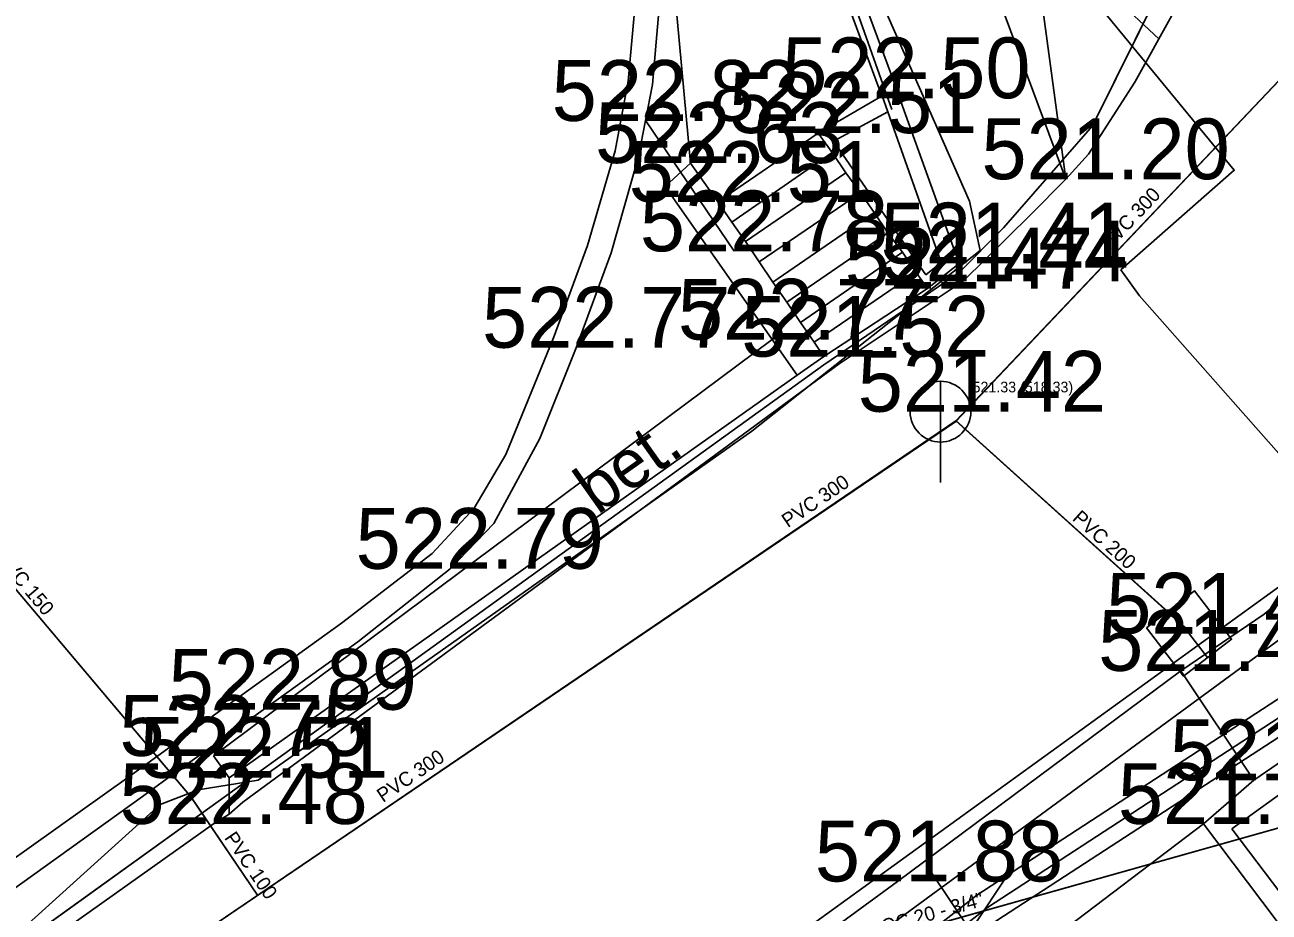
# Model space of a CAD drawing. Extents: x -668867 to -667827, y -1131943 to -1131019.
# Drawn here: x -668551.42 to -668536.05, y -1131435.74 to -1131424.78 of the extents above; entities that cross this region are included whole.
import ezdxf

# ---------------------------------------------------------------- set-up
doc = ezdxf.new("R2010")
doc.units = 0
for name, color, linetype in [('G_Bod_tecka', 7, 'Continuous'), ('G_Bod_vyska', 7, 'Continuous'), ('G_Breh_Teren', 7, 'Continuous'), ('G_Cesty_Schody', 7, 'Continuous'), ('G_Plochy_zpevnene', 7, 'Continuous'), ('G_Ploty', 7, 'Continuous'), ('G_Ploty_vstupy', 7, 'Continuous'), ('G_Popisy_povrchu', 7, 'Continuous'), ('G_Site-kanalizace', 7, 'Continuous'), ('G_Vyskove_srafy', 7, 'Continuous'), ('G_Z_CHRANICKA-TEPLOVOD_kotovane', 7, 'Continuous'), ('G_Z_ELsilove_podz_kotovane', 7, 'Continuous'), ('G_Z_KANAL_podz_kotovane', 7, 'Continuous'), ('G_Z_PLYNY_podz_geodeticky', 7, 'Continuous'), ('G_Z_SPOJE_podz_geodeticky', 7, 'Continuous'), ('G_Z_SPOJE_podz_kotovane', 7, 'Continuous'), ('G_Z_SPOJE_podz_priblizne', 7, 'Continuous'), ('G_Z_VODA_podz_kotovane', 7, 'Continuous'), ('G_Zabradli_Svodidla', 7, 'Continuous'), ('G_Zelen-Znacky', 7, 'Continuous'), ('Vrstva 12', 7, 'Continuous'), ('Vrstva 17', 7, 'Continuous'), ('Vrstva 2', 7, 'Continuous'), ('Vrstva 25', 7, 'Continuous'), ('Vrstva 3', 7, 'Continuous'), ('Vrstva 4', 7, 'Continuous'), ('Vrstva 8', 7, 'Continuous')]:
    doc.layers.add(name, color=color, linetype=linetype)

msp = doc.modelspace()

# ---------------------------------------------------------------- linework, layer by layer
at = {"layer": 'G_Bod_tecka'}
for p, q in [((-668540.88, -1131425.69), (-668540.88, -1131425.69)), ((-668543.75, -1131425.97), (-668543.75, -1131425.97)), ((-668541.62, -1131426.12), (-668541.62, -1131426.12)), ((-668543.2, -1131426.49), (-668543.2, -1131426.49)), ((-668538.56, -1131426.69), (-668538.56, -1131426.69)), ((-668542.86, -1131426.97), (-668542.86, -1131426.97)), ((-668542.66, -1131427.58), (-668542.66, -1131427.58)), ((-668539.89, -1131427.73), (-668539.89, -1131427.73)), ((-668539.83, -1131427.95), (-668539.83, -1131427.95)), ((-668540.27, -1131428.04), (-668540.27, -1131428.04)), ((-668544.61, -1131428.77), (-668544.61, -1131428.77)), ((-668542.19, -1131428.67), (-668542.19, -1131428.67)), ((-668541.55, -1131428.88), (-668541.55, -1131428.88)), ((-668540.11, -1131429.56), (-668540.11, -1131429.56)), ((-668546.17, -1131431.5), (-668546.17, -1131431.5)), ((-668537.04, -1131432.3), (-668537.04, -1131432.3)), ((-668537.14, -1131432.76), (-668537.14, -1131432.76)), ((-668548.48, -1131433.24), (-668548.48, -1131433.24)), ((-668549.09, -1131433.81), (-668549.09, -1131433.81)), ((-668548.9, -1131434.08), (-668548.9, -1131434.08)), ((-668536.24, -1131434.11), (-668536.24, -1131434.11)), ((-668549.09, -1131434.65), (-668549.09, -1131434.65)), ((-668536.86, -1131434.65), (-668536.86, -1131434.65)), ((-668540.64, -1131435.36), (-668540.64, -1131435.36))]:
    msp.add_line(p, q, dxfattribs=at)
at = {"layer": 'G_Breh_Teren'}
msp.add_line((-668538.56, -1131426.69), (-668539.19, -1131422.04), dxfattribs=at)
at = {"layer": 'G_Cesty_Schody'}
for p, q in [((-668540.83, -1131425.66), (-668540.76, -1131425.86)), ((-668541.62, -1131426.12), (-668542.86, -1131426.97)), ((-668541.62, -1131426.12), (-668541.53, -1131426.07)), ((-668541.45, -1131426.36), (-668541.62, -1131426.12)), ((-668541.43, -1131426.22), (-668541.53, -1131426.07)), ((-668540.29, -1131427.87), (-668541.43, -1131426.22)), ((-668541.45, -1131426.36), (-668542.69, -1131427.22)), ((-668541.28, -1131426.61), (-668541.45, -1131426.36)), ((-668543.51, -1131426.78), (-668543.2, -1131426.49)), ((-668543.2, -1131426.49), (-668542.86, -1131426.97)), ((-668541.28, -1131426.61), (-668542.52, -1131427.46)), ((-668541.1, -1131426.86), (-668541.28, -1131426.61)), ((-668542.19, -1131428.67), (-668543.51, -1131426.78)), ((-668541.1, -1131426.86), (-668542.35, -1131427.71)), ((-668540.93, -1131427.1), (-668541.1, -1131426.86)), ((-668542.86, -1131426.97), (-668542.69, -1131427.22)), ((-668542.69, -1131427.22), (-668542.52, -1131427.46)), ((-668540.93, -1131427.1), (-668542.18, -1131427.96)), ((-668540.76, -1131427.35), (-668540.93, -1131427.1)), ((-668540.76, -1131427.35), (-668542.01, -1131428.21)), ((-668540.58, -1131427.59), (-668540.76, -1131427.35)), ((-668542.52, -1131427.46), (-668542.35, -1131427.71)), ((-668540.58, -1131427.59), (-668541.84, -1131428.46)), ((-668540.41, -1131427.84), (-668540.58, -1131427.59)), ((-668542.35, -1131427.71), (-668542.18, -1131427.96)), ((-668540.41, -1131427.84), (-668541.67, -1131428.7)), ((-668540.27, -1131428.04), (-668540.41, -1131427.84)), ((-668542.18, -1131427.96), (-668542.01, -1131428.21)), ((-668541.55, -1131428.88), (-668540.27, -1131428.04)), ((-668542.01, -1131428.21), (-668541.84, -1131428.46)), ((-668541.84, -1131428.46), (-668541.67, -1131428.7)), ((-668541.88, -1131429.11), (-668542.19, -1131428.67)), ((-668541.67, -1131428.7), (-668541.55, -1131428.88)), ((-668541.88, -1131429.11), (-668541.55, -1131428.88))]:
    msp.add_line(p, q, dxfattribs=at)
at = {"layer": 'G_Plochy_zpevnene'}
for p, q in [((-668543.56, -1131422.6), (-668543.2, -1131426.49)), ((-668540.88, -1131425.54), (-668541.86, -1131422.88)), ((-668541.68, -1131422.8), (-668540.69, -1131425.47)), ((-668540.88, -1131425.54), (-668540.83, -1131425.66)), ((-668540.69, -1131425.47), (-668540.58, -1131425.79)), ((-668538.28, -1131426.38), (-668537.71, -1131425.49)), ((-668541.53, -1131426.07), (-668540.83, -1131425.66)), ((-668540.58, -1131425.79), (-668539.88, -1131427.73)), ((-668541.43, -1131426.22), (-668540.76, -1131425.86)), ((-668540.76, -1131425.86), (-668540.71, -1131426)), ((-668540.71, -1131426), (-668540.1, -1131427.72)), ((-668538.56, -1131426.69), (-668538.28, -1131426.38)), ((-668539, -1131427.13), (-668538.56, -1131426.69)), ((-668539.83, -1131427.95), (-668539, -1131427.13)), ((-668540.1, -1131427.72), (-668540.29, -1131427.87)), ((-668539.88, -1131427.73), (-668540.27, -1131428.04)), ((-668541.36, -1131428.97), (-668539.83, -1131427.95)), ((-668542.19, -1131428.67), (-668549.09, -1131433.81)), ((-668541.88, -1131429.11), (-668548.9, -1131434.08)), ((-668540.64, -1131435.36), (-668537.14, -1131432.76)), ((-668537.14, -1131432.76), (-668536.24, -1131434.11)), ((-668548.9, -1131434.08), (-668549.09, -1131433.81)), ((-668548.9, -1131434.53), (-668548.9, -1131434.08))]:
    msp.add_line(p, q, dxfattribs=at)
for points in [[(-668541.28, -1131419.29), (-668540.06, -1131422.66), (-668538.56, -1131426.69)], [(-668537.71, -1131425.49), (-668537.23, -1131424.63), (-668536.74, -1131423.38)], [(-668530.98, -1131423.5), (-668531.23, -1131424.72), (-668531.6, -1131425.93), (-668532.09, -1131427.12), (-668532.7, -1131428.26), (-668533.41, -1131429.34), (-668534.23, -1131430.34), (-668535.13, -1131431.25), (-668536.11, -1131432.06), (-668537.14, -1131432.76)], [(-668548.9, -1131434.53), (-668548.73, -1131434.38), (-668541.36, -1131428.97)], [(-668555.34, -1131439.08), (-668549.09, -1131434.65), (-668548.9, -1131434.53)], [(-668540.64, -1131435.36), (-668547.5, -1131440.38)]]:
    msp.add_lwpolyline(points, dxfattribs=at)
at = {"layer": 'G_Ploty'}
for p, q in [((-668545.48, -1131430.09), (-668545.87, -1131430.75)), ((-668536.51, -1131434.71), (-668534.96, -1131433.59)), ((-668534.8, -1131437.38), (-668536.86, -1131434.65)), ((-668534.75, -1131437.04), (-668536.51, -1131434.71))]:
    msp.add_line(p, q, dxfattribs=at)
for points in [[(-668546.17, -1131431.5), (-668545.63, -1131430.94), (-668545.06, -1131429.89), (-668544.61, -1131428.77), (-668544.18, -1131427.6), (-668543.84, -1131426.41), (-668543.67, -1131425.52), (-668543.59, -1131424.62), (-668543.66, -1131423.43), (-668543.76, -1131422.45), (-668544.33, -1131419.8), (-668545.21, -1131418.05), (-668546.52, -1131416), (-668548.82, -1131412.9), (-668551.11, -1131409.79)], [(-668551.31, -1131409.94), (-668549.04, -1131413.05), (-668546.77, -1131416.16), (-668545.49, -1131418.18), (-668544.6, -1131419.87), (-668544.02, -1131422.48), (-668543.89, -1131424.62), (-668543.97, -1131425.48), (-668544.13, -1131426.34), (-668544.47, -1131427.51), (-668544.89, -1131428.65), (-668545.48, -1131430.09)], [(-668545.87, -1131430.75), (-668546.39, -1131431.31), (-668547.51, -1131432.17)], [(-668549.53, -1131433.99), (-668548.48, -1131433.24), (-668547.31, -1131432.4), (-668546.17, -1131431.5)], [(-668547.51, -1131432.17), (-668548.66, -1131433), (-668550.14, -1131434.07), (-668551.64, -1131435.14), (-668551.85, -1131435.29), (-668560.64, -1131441.64)], [(-668536.86, -1131434.65), (-668536.24, -1131434.11), (-668533.83, -1131432.46)], [(-668560.49, -1131441.85), (-668551.68, -1131435.54), (-668551.46, -1131435.38), (-668549.97, -1131434.31), (-668549.53, -1131433.99)]]:
    msp.add_lwpolyline(points, dxfattribs=at)
at = {"layer": 'G_Ploty_vstupy'}
msp.add_line((-668536.86, -1131434.65), (-668540.06, -1131437.07), dxfattribs=at)
at = {"layer": 'G_Site-kanalizace'}
for p, q in [((-668540.11, -1131429.185), (-668540.11, -1131430.435)), ((-668537.268, -1131432.003), (-668536.812, -1131432.597))]:
    msp.add_line(p, q, dxfattribs=at)
msp.add_lwpolyline([(-668537.565, -1131432.23), (-668537.108, -1131432.825), (-668536.513, -1131432.369), (-668536.97, -1131431.774)], close=True, dxfattribs=at)
msp.add_circle((-668540.11, -1131429.56), 0.375, dxfattribs=at)
at = {"layer": 'G_Vyskove_srafy'}
msp.add_line((-668539, -1131423.47), (-668537.41, -1131424.96), dxfattribs=at)
at = {"layer": 'G_Z_CHRANICKA-TEPLOVOD_kotovane'}
msp.add_lwpolyline([(-668529.776, -1131427.261), (-668529.588, -1131427.055), (-668529.44, -1131427.19), (-668529.292, -1131427.325), (-668531.278, -1131429.501), (-668535.177, -1131433.089), (-668539.414, -1131435.843), (-668542.517, -1131438.267), (-668542.763, -1131437.952), (-668539.66, -1131435.528), (-668535.423, -1131432.771), (-668531.562, -1131429.219)], close=True, dxfattribs=at)
at = {"layer": 'G_Z_ELsilove_podz_kotovane'}
for points in [[(-668606.76, -1131475.72), (-668596.23, -1131468.15), (-668582.24, -1131458.18), (-668582.12, -1131457.77), (-668581.98, -1131458), (-668572.21, -1131450.91), (-668559.32, -1131441.76), (-668559.2, -1131441.49), (-668559.08, -1131441.59), (-668548.93, -1131434.3), (-668541.55, -1131428.98), (-668539.88, -1131427.84), (-668539.33, -1131427.29), (-668538.23, -1131426.03), (-668536.78, -1131423.1), (-668537.01, -1131423.01)], [(-668528.019, -1131427.391), (-668528.429, -1131426.965), (-668529.577, -1131427.34), (-668531.42, -1131429.36), (-668535.3, -1131432.93), (-668539.53, -1131435.68), (-668542.64, -1131438.11), (-668544.01, -1131439.1), (-668545.43, -1131440.03), (-668548.36, -1131442.17), (-668551.01, -1131444.12), (-668553.349, -1131445.928)]]:
    msp.add_lwpolyline(points, dxfattribs=at)
at = {"layer": 'G_Z_KANAL_podz_kotovane'}
for p, q in [((-668539.92, -1131429.68), (-668527.51, -1131416.6)), ((-668554.32, -1131428.46), (-668549.37, -1131434.32)), ((-668560.22, -1131443.45), (-668539.92, -1131429.68)), ((-668537, -1131432.3), (-668539.92, -1131429.67)), ((-668549.37, -1131434.32), (-668548.55, -1131435.53))]:
    msp.add_line(p, q, dxfattribs=at)
at = {"layer": 'G_Z_PLYNY_podz_geodeticky'}
for points in [[(-668539.19, -1131423.28), (-668536.48, -1131426.58), (-668537.88, -1131427.81), (-668537.65, -1131428.13)], [(-668535.07, -1131431.1), (-668535.43, -1131430.64), (-668537.65, -1131428.13)], [(-668552.01, -1131443.25), (-668541.65, -1131435.86), (-668535.07, -1131431.1)]]:
    msp.add_lwpolyline(points, dxfattribs=at)
at = {"layer": 'G_Z_SPOJE_podz_geodeticky'}
for points in [[(-668577.41, -1131372.64), (-668576.75, -1131372.81), (-668574.72, -1131375.63), (-668571.66, -1131379.63), (-668569.93, -1131382), (-668566.96, -1131386.01), (-668566.38, -1131386.07), (-668554.43, -1131402.33), (-668544.84, -1131415.34), (-668542.78, -1131418.73), (-668542.11, -1131420.92), (-668541.19, -1131423.7), (-668539.75, -1131426.96), (-668539.62, -1131427.57), (-668542.44, -1131429.8), (-668548.54, -1131434.11), (-668549.28, -1131434.23), (-668549.75, -1131434.41), (-668552.5, -1131436.89), (-668555.29, -1131438.73), (-668558.67, -1131441.06), (-668558.78, -1131441.24), (-668563.11, -1131444.25), (-668563.75, -1131444.7)], [(-668630.08, -1131499.28), (-668624.53, -1131495.85), (-668617.01, -1131490.03), (-668604.39, -1131481.12), (-668597.72, -1131476.52), (-668583.85, -1131466.82), (-668575.85, -1131461.06), (-668561.49, -1131450.61), (-668553.3, -1131445.12), (-668533.18, -1131430.36), (-668529.93, -1131427.14), (-668529.54, -1131425.97), (-668529.81, -1131424.67), (-668530.52, -1131423.47)]]:
    msp.add_lwpolyline(points, dxfattribs=at)
at = {"layer": 'G_Z_SPOJE_podz_kotovane'}
msp.add_lwpolyline([(-668577.41, -1131372.64), (-668576.75, -1131372.81), (-668574.72, -1131375.63), (-668571.66, -1131379.63), (-668569.93, -1131382), (-668566.96, -1131386.01), (-668566.38, -1131386.07), (-668554.43, -1131402.33), (-668544.84, -1131415.34), (-668542.78, -1131418.73), (-668542.11, -1131420.92), (-668541.19, -1131423.7), (-668539.75, -1131426.96), (-668539.62, -1131427.57), (-668542.44, -1131429.8), (-668548.54, -1131434.11), (-668549.28, -1131434.23), (-668549.75, -1131434.41), (-668552.5, -1131436.89), (-668555.29, -1131438.73), (-668558.67, -1131441.06), (-668558.78, -1131441.24), (-668563.11, -1131444.25), (-668563.75, -1131444.7)], dxfattribs=at)
at = {"layer": 'G_Z_SPOJE_podz_priblizne'}
for points in [[(-668577.41, -1131372.64), (-668576.75, -1131372.81), (-668574.72, -1131375.63), (-668571.66, -1131379.63), (-668569.93, -1131382), (-668566.96, -1131386.01), (-668566.38, -1131386.07), (-668554.43, -1131402.33), (-668544.84, -1131415.34), (-668542.78, -1131418.73), (-668542.11, -1131420.92), (-668541.19, -1131423.7), (-668539.75, -1131426.96), (-668539.62, -1131427.57), (-668542.44, -1131429.8), (-668548.54, -1131434.11), (-668549.28, -1131434.23), (-668549.75, -1131434.41), (-668552.5, -1131436.89), (-668555.29, -1131438.73), (-668558.67, -1131441.06), (-668558.78, -1131441.24), (-668563.11, -1131444.25), (-668563.75, -1131444.7)], [(-668630.08, -1131499.28), (-668624.53, -1131495.85), (-668617.01, -1131490.03), (-668604.39, -1131481.12), (-668597.72, -1131476.52), (-668583.85, -1131466.82), (-668575.85, -1131461.06), (-668561.49, -1131450.61), (-668553.3, -1131445.12), (-668533.18, -1131430.36), (-668529.93, -1131427.14), (-668529.54, -1131425.97), (-668529.81, -1131424.67), (-668530.52, -1131423.47)]]:
    msp.add_lwpolyline(points, dxfattribs=at)
at = {"layer": 'G_Z_VODA_podz_kotovane'}
msp.add_lwpolyline([(-668554.5, -1131439.75), (-668554.07, -1131439.8), (-668532.27, -1131433.67)], dxfattribs=at)
at = {"layer": 'G_Zabradli_Svodidla'}
for p, q in [((-668540.71, -1131425.83), (-668542.96, -1131419.48)), ((-668543.75, -1131425.97), (-668542.66, -1131427.58))]:
    msp.add_line(p, q, dxfattribs=at)
at = {"layer": 'G_Zelen-Znacky'}
for p, q in [((-668540.24, -1131435.22), (-668539.74, -1131435.97)), ((-668539.74, -1131435.97), (-668539.24, -1131435.22))]:
    msp.add_line(p, q, dxfattribs=at)
at = {"layer": 'Vrstva 12'}
for p, q in [((-668539.92, -1131429.675), (-668527.513, -1131416.6)), ((-668554.32, -1131428.46), (-668549.371, -1131434.317)), ((-668560.215, -1131443.447), (-668539.92, -1131429.675)), ((-668537.004, -1131432.302), (-668539.92, -1131429.675)), ((-668549.371, -1131434.317), (-668548.548, -1131435.53))]:
    msp.add_line(p, q, dxfattribs=at)
at = {"layer": 'Vrstva 17'}
for p, q in [((-668538.23, -1131426.03), (-668536.78, -1131423.1)), ((-668539.33, -1131427.29), (-668538.23, -1131426.03)), ((-668539.88, -1131427.84), (-668539.33, -1131427.29)), ((-668541.55, -1131428.98), (-668539.88, -1131427.84)), ((-668548.93, -1131434.3), (-668541.55, -1131428.98)), ((-668559.08, -1131441.59), (-668548.93, -1131434.3))]:
    msp.add_line(p, q, dxfattribs=at)
at = {"layer": 'Vrstva 25'}
msp.add_lwpolyline([(-668554.499, -1131439.751), (-668554.07, -1131439.798), (-668532.268, -1131433.671)], dxfattribs=at)
at = {"layer": 'Vrstva 8'}
msp.add_line((-668539.92, -1131429.675), (-668539.92, -1131429.675), dxfattribs=at)

# ---------------------------------------------------------------- texts
at = {"layer": 'G_Bod_vyska'}
for s, p in [('522.50', (-668542.066, -1131425.69)), ('522.82', (-668544.914, -1131425.97)), ('522.51', (-668542.722, -1131426.12)), ('522.63', (-668544.378, -1131426.49)), ('521.20', (-668539.604, -1131426.69)), ('522.51', (-668543.962, -1131426.97)), ('522.78', (-668543.824, -1131427.58)), ('521.41', (-668540.851, -1131427.73)), ('521.44', (-668540.852, -1131427.95)), ('521.47', (-668541.292, -1131428.04)), ('522.77', (-668545.774, -1131428.77)), ('522.77', (-668543.354, -1131428.67)), ('521.52', (-668542.572, -1131428.88)), ('521.42', (-668541.132, -1131429.56)), ('522.79', (-668547.336, -1131431.5)), ('521.48', (-668538.062, -1131432.3)), ('521.44', (-668538.162, -1131432.76)), ('522.89', (-668549.646, -1131433.24)), ('522.75', (-668550.254, -1131433.81)), ('522.51', (-668550.002, -1131434.08)), ('521.63', (-668537.276, -1131434.11)), ('522.48', (-668550.254, -1131434.65)), ('521.60', (-668537.918, -1131434.65)), ('521.88', (-668541.662, -1131435.36))]:
    msp.add_text(s, height=0.75, dxfattribs=at).set_placement(p)
at = {"layer": 'G_Popisy_povrchu'}
msp.add_text('bet.', height=0.6, rotation=35.303, dxfattribs=at).set_placement((-668544.348, -1131430.841))
at = {"layer": 'Vrstva 2'}
msp.add_text('521.33 (518.33)', height=0.13163, dxfattribs=at).set_placement((-668539.714, -1131429.322))
at = {"layer": 'Vrstva 3'}
for s, rotation, p in [('PVC 300', 46.5274, (-668538.025, -1131427.575)), ('PVC 300', 34.1758, (-668541.996, -1131430.999)), ('PVC 200', 317.9951, (-668538.492, -1131430.891)), ('PVC 150', 310.2104, (-668551.788, -1131431.375)), ('PVC 300', 34.1758, (-668546.998, -1131434.392)), ('PVC 100', 304.2179, (-668548.965, -1131434.822))]:
    msp.add_text(s, height=0.1755, rotation=rotation, dxfattribs=at).set_placement(p)
at = {"layer": 'Vrstva 4'}
msp.add_text('OC 20 - 3/4"', height=0.17551, rotation=15.7005, dxfattribs=at).set_placement((-668540.811, -1131436.008))

doc.saveas('drawing.dxf')
